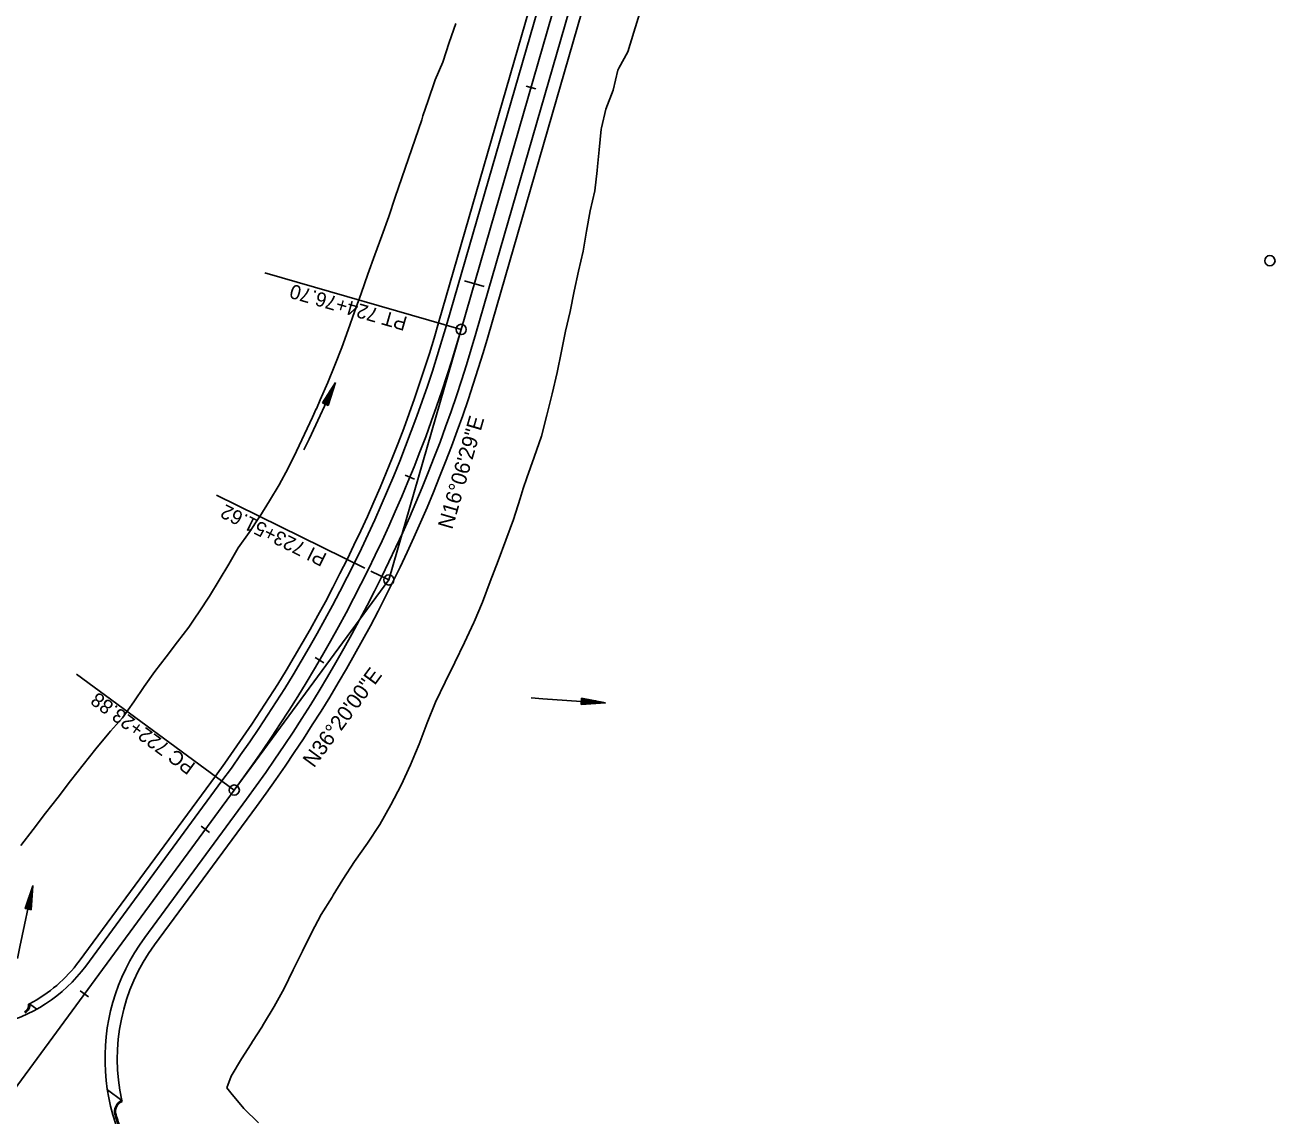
# Model space of a CAD drawing. Extents: x 1300404 to 1323571, y 234004 to 252077.
# Drawn here: x 1311254 to 1311867, y 240523 to 241056 of the extents above; entities that cross this region are included whole.
import ezdxf

# ---------------------------------------------------------------- set-up
doc = ezdxf.new("R2010")
doc.units = 0
for name, color, linetype in [('R_Const Limits', 7, 'Continuous'), ('R_Curb', 7, 'Continuous'), ('R_Flow Arrows', 7, 'Continuous'), ('R_Horz Alg Annot', 7, 'Continuous'), ('R_Horz Alg Annot Leader', 7, 'Continuous'), ('R_Horz Alg Major Ticks', 7, 'Continuous'), ('R_Horz Alg Minor Ticks', 7, 'Continuous'), ('R_Horz Alg Tangents', 7, 'Continuous'), ('R_Horz Alg Tangents Text', 7, 'Continuous'), ('R_Lane Edge', 7, 'Continuous'), ('R_Proposed', 7, 'Continuous'), ('R_Shoulder', 7, 'Continuous')]:
    doc.layers.add(name, color=color, linetype=linetype)

msp = doc.modelspace()

# ---------------------------------------------------------------- linework, layer by layer
at = {"layer": 'R_Const Limits'}
for points in [[(1311555.44, 241062.48), (1311552.59, 241052.89), (1311549.67, 241043.33), (1311545.17, 241035.34), (1311544.69, 241034.36), (1311542.46, 241024.6), (1311538.76, 241015.26), (1311536.65, 241006.06), (1311536.59, 241005.47), (1311535.54, 240995.37), (1311534.82, 240987.2), (1311534.65, 240985.22), (1311533.46, 240975.15), (1311531.22, 240965.39), (1311529.45, 240955.49), (1311527.66, 240945.6), (1311525.48, 240935.82), (1311523.25, 240926.06), (1311521.35, 240916.2), (1311519.03, 240906.46), (1311517.1, 240896.61), (1311515, 240886.31), (1311512.61, 240875.83), (1311510.02, 240865.39), (1311507.27, 240854.99), (1311503.78, 240844.83), (1311500.22, 240834.68), (1311498.32, 240829.38), (1311498.32, 240829.38), (1311496.87, 240824.45), (1311493.62, 240814.17), (1311489.82, 240804.08), (1311486.09, 240793.95), (1311482.24, 240783.86), (1311478.43, 240773.73), (1311474.33, 240764.06), (1311474.19, 240763.78), (1311469.62, 240753.98), (1311464.94, 240744.22), (1311460.1, 240734.54), (1311455.46, 240724.73), (1311451.41, 240714.56), (1311447.49, 240704.25), (1311445.71, 240700.01), (1311445.7, 240700.01), (1311443.18, 240694.12), (1311438.54, 240684.15), (1311433.48, 240674.4), (1311428.12, 240664.82), (1311422.11, 240655.66), (1311415.82, 240646.7), (1311409.97, 240637.86), (1311405.38, 240630.29), (1311404.76, 240629.28), (1311399.38, 240620.82), (1311394.77, 240611.8), (1311390.23, 240602.72), (1311385.79, 240593.58), (1311381.29, 240584.48), (1311376.36, 240575.69), (1311371.2, 240567.07), (1311370.33, 240565.6), (1311365.88, 240558.57), (1311365.17, 240557.39), (1311360.46, 240550.14), (1311355.33, 240541.5), (1311353.2, 240535.86)], [(1311252.34, 240654.48), (1311258.42, 240662.43), (1311264.52, 240670.35), (1311270.65, 240678.26), (1311276.74, 240686.19), (1311282.96, 240694.03), (1311289.17, 240701.88), (1311295.49, 240709.64), (1311296.22, 240710.58), (1311302.18, 240717.14), (1311307.63, 240724.85), (1311312.72, 240732.38), (1311318.04, 240739.75), (1311323.55, 240747), (1311329.13, 240754.24), (1311334.56, 240761.58), (1311337.63, 240765.92), (1311337.63, 240765.93), (1311339.76, 240769.09), (1311344.79, 240776.72), (1311349.57, 240784.5), (1311354.22, 240792.37), (1311358.78, 240800.3), (1311364.13, 240807.82), (1311369.23, 240815.52), (1311369.37, 240815.75), (1311374.13, 240823.35), (1311378.85, 240831.29), (1311383.24, 240839.41), (1311387.29, 240847.7), (1311391.33, 240856), (1311395.23, 240864.38), (1311397.07, 240868.37), (1311397.08, 240868.38), (1311399.03, 240872.81), (1311402.68, 240881.31), (1311406.21, 240889.87), (1311409.51, 240898.52), (1311412.73, 240907.22), (1311415.81, 240915.96), (1311419.03, 240924.93), (1311422.31, 240934.39), (1311425.65, 240943.83), (1311429.1, 240953.25), (1311432.51, 240962.67), (1311435.75, 240972.14), (1311438.99, 240981.62), (1311442.24, 240991.09), (1311445.44, 241000.57), (1311448.67, 241010.05), (1311449.29, 241011.9), (1311451.85, 241019.54), (1311455.03, 241029.03), (1311455.21, 241029.58), (1311458.96, 241038.3), (1311462.11, 241047.8), (1311465.46, 241057.24)], [(1311353.2, 240535.86), (1311355.14, 240533.39), (1311361.62, 240525.75), (1311368.7, 240518.68)]]:
    msp.add_lwpolyline(points, dxfattribs=at)
at = {"layer": 'R_Curb'}
for centre, radius, start, end in [((1311252.75, 240576.22), 3.5, 294.48881, 9.25521), ((1311252.75, 240576.22), 4, 294.48881, 11.59092), ((1311304.27, 240524.22), 6, 113.98173, 196.20549), ((1311304.27, 240524.22), 5.5, 115.0194, 196.20549), ((1311393.58, 240550.17), 99, 196.20549, 199.75076), ((1311393.58, 240550.17), 98.5, 196.20549, 200.41529)]:
    msp.add_arc(centre, radius, start, end, dxfattribs=at)
at = {"layer": 'R_Flow Arrows'}
for p, q in [((1311400.13, 240871.35), (1311406.39, 240881.42)), ((1311402.9, 240870.09), (1311406.39, 240881.42)), ((1311402.9, 240870.09), (1311400.13, 240871.35)), ((1311526.79, 240723.64), (1311526.97, 240726.67)), ((1311526.79, 240723.64), (1311538.61, 240724.45)), ((1311526.97, 240726.67), (1311538.61, 240724.45)), ((1311254.41, 240623.66), (1311258.21, 240634.88)), ((1311257.39, 240623.06), (1311258.21, 240634.88)), ((1311254.41, 240623.66), (1311257.39, 240623.06))]:
    msp.add_line(p, q, dxfattribs=at)
for points in [[(1311391.03, 240848.31), (1311393.49, 240853.53), (1311406.52, 240881.35)], [(1311400.96, 240870.98), (1311403.54, 240876.63), (1311403.88, 240877.39)], [(1311401.24, 240870.85), (1311403.81, 240876.51), (1311405.13, 240879.41)], [(1311401.79, 240870.6), (1311404.37, 240876.26), (1311405.68, 240879.16)], [(1311400.41, 240871.23), (1311401.38, 240873.37)], [(1311400.68, 240871.1), (1311402.63, 240875.38)], [(1311402.07, 240870.47), (1311404.65, 240876.13), (1311404.99, 240876.89)], [(1311402.34, 240870.35), (1311404.29, 240874.62)], [(1311402.62, 240870.22), (1311403.6, 240872.36)], [(1311502.2, 240726.87), (1311507.94, 240726.45), (1311538.59, 240724.3)], [(1311526.84, 240724.55), (1311533.05, 240724.18), (1311533.88, 240724.13)], [(1311526.86, 240724.85), (1311533.07, 240724.48), (1311536.24, 240724.3)], [(1311526.9, 240725.46), (1311533.1, 240725.09), (1311536.28, 240724.91)], [(1311526.91, 240725.76), (1311533.12, 240725.39), (1311533.95, 240725.34)], [(1311526.93, 240726.06), (1311531.62, 240725.78)], [(1311526.95, 240726.37), (1311529.3, 240726.23)], [(1311526.8, 240723.94), (1311529.15, 240723.8)], [(1311526.82, 240724.24), (1311531.51, 240723.96)], [(1311250.72, 240599.22), (1311251.9, 240604.86), (1311258.26, 240634.92)], [(1311255.6, 240623.42), (1311256.83, 240629.52), (1311257.46, 240632.63)], [(1311255.01, 240623.54), (1311255.93, 240628.15)], [(1311255.31, 240623.48), (1311256.53, 240629.58), (1311256.7, 240630.39)], [(1311256.2, 240623.3), (1311257.42, 240629.39), (1311258.06, 240632.51)], [(1311256.5, 240623.24), (1311257.72, 240629.33), (1311257.89, 240630.15)], [(1311256.8, 240623.18), (1311257.72, 240627.79)], [(1311254.71, 240623.6), (1311255.17, 240625.9)], [(1311257.1, 240623.12), (1311257.56, 240625.42)]]:
    msp.add_lwpolyline(points, dxfattribs=at)
at = {"layer": 'R_Horz Alg Annot Leader'}
for points in [[(1311468.01, 240907.35), (1311371.93, 240935.09)], [(1311468.01, 240907.35), (1311371.93, 240935.09)], [(1311420.75, 240790.45), (1311348.2, 240826.18)], [(1311420.75, 240790.45), (1311348.2, 240826.18)], [(1311432.57, 240784.63), (1311423.68, 240789.01)], [(1311432.57, 240784.63), (1311423.68, 240789.01)], [(1311356.89, 240681.72), (1311279.62, 240738.55)], [(1311356.89, 240681.72), (1311279.62, 240738.55)]]:
    msp.add_lwpolyline(points, dxfattribs=at)
at = {"layer": 'R_Horz Alg Major Ticks'}
msp.add_lwpolyline([(1311469.67, 240931.12), (1311479.28, 240928.35)], dxfattribs=at)
msp.add_lwpolyline([(1311469.67, 240931.12), (1311479.28, 240928.35)], dxfattribs=at)
at = {"layer": 'R_Horz Alg Minor Ticks'}
for points in [[(1311499.82, 241026.5), (1311504.62, 241025.11)], [(1311499.82, 241026.5), (1311504.62, 241025.11)], [(1311440.51, 240835.89), (1311445.14, 240833.99)], [(1311440.51, 240835.89), (1311445.14, 240833.99)], [(1311396.48, 240746.58), (1311400.8, 240744.06)], [(1311396.48, 240746.58), (1311400.8, 240744.06)], [(1311340.72, 240663.96), (1311344.75, 240661)], [(1311340.72, 240663.96), (1311344.75, 240661)], [(1311281.47, 240583.41), (1311285.5, 240580.44)], [(1311281.47, 240583.41), (1311285.5, 240580.44)]]:
    msp.add_lwpolyline(points, dxfattribs=at)
at = {"layer": 'R_Horz Alg Tangents'}
for p, q in [((1311432.57, 240784.63), (1311468.01, 240907.35)), ((1311432.57, 240784.63), (1311468.01, 240907.35)), ((1311356.89, 240681.72), (1311432.57, 240784.63)), ((1311356.89, 240681.72), (1311432.57, 240784.63))]:
    msp.add_line(p, q, dxfattribs=at)
at = {"layer": 'R_Lane Edge'}
for p, q in [((1311460.8, 240909.43), (1311563.29, 241264.31)), ((1311475.21, 240905.27), (1311577.7, 241260.15)), ((1311284.15, 240595.49), (1311350.84, 240686.17)), ((1311313.02, 240609.42), (1311362.93, 240677.28)), ((1311256.67, 240577.02), (1311256.2, 240576.78)), ((1311256.67, 240577.02), (1311260.23, 240574.4)), ((1311301.83, 240529.7), (1311294.75, 240534.91)), ((1311301.95, 240529.2), (1311301.83, 240529.7))]:
    msp.add_line(p, q, dxfattribs=at)
for centre, radius, start, end in [((1310779.93, 241106.06), 708.7, 323.66667, 343.89183), ((1310779.93, 241106.06), 723.7, 323.66667, 343.89183), ((1311393.58, 240550.17), 100, 143.66667, 223.66667), ((1311223.73, 240639.92), 75, 282.23981, 323.66667)]:
    msp.add_arc(centre, radius, start, end, dxfattribs=at)
at = {"layer": 'R_Proposed'}
for p, q in [((1311468.01, 240907.35), (1311570.49, 241262.23)), ((1311468.01, 240907.35), (1311570.49, 241262.23)), ((1311241.2, 240524.43), (1311356.89, 240681.72)), ((1311241.2, 240524.43), (1311356.89, 240681.72))]:
    msp.add_line(p, q, dxfattribs=at)
for centre in [(1311864.02, 240941.01), (1311468.01, 240907.35), (1311468.01, 240907.35), (1311432.57, 240784.63), (1311432.57, 240784.63), (1311356.89, 240681.72), (1311356.89, 240681.72)]:
    msp.add_circle(centre, 2.5, dxfattribs=at)
msp.add_arc((1310779.93, 241106.06), 716.2, 323.66667, 343.89183, dxfattribs=at)
msp.add_arc((1310779.93, 241106.06), 716.2, 323.66667, 343.89183, dxfattribs=at)
at = {"layer": 'R_Shoulder'}
for p, q in [((1311456.96, 240910.54), (1311559.45, 241265.42)), ((1311480.98, 240903.6), (1311583.46, 241258.48)), ((1311280.93, 240597.86), (1311347.62, 240688.54)), ((1311317.85, 240605.87), (1311367.76, 240673.73))]:
    msp.add_line(p, q, dxfattribs=at)
for centre, radius, start, end in [((1310779.93, 241106.06), 704.7, 323.66667, 343.89183), ((1310779.93, 241106.06), 729.7, 323.66667, 343.89183), ((1311393.58, 240550.17), 94, 143.66667, 192.57952), ((1311223.73, 240639.92), 71, 297.63688, 323.66667)]:
    msp.add_arc(centre, radius, start, end, dxfattribs=at)

# ---------------------------------------------------------------- texts
at = {"layer": 'R_Horz Alg Annot'}
for s, rotation, p in [('PT 724+76.70', 163.89183, (1311442.1, 240913.27)), ('PT 724+76.70', 163.89183, (1311442.1, 240913.27)), ('PI 723+51.62', 153.77925, (1311402.73, 240797.18)), ('PI 723+51.62', 153.77925, (1311402.73, 240797.18)), ('PC 722+23.88', 143.66667, (1311338.41, 240694.41)), ('PC 722+23.88', 143.66667, (1311338.41, 240694.41))]:
    msp.add_text(s, height=7, rotation=rotation, dxfattribs=at).set_placement(p)
at = {"layer": 'R_Horz Alg Tangents Text'}
for s, rotation, p in [('N16%%d06\'29"E', 73.89183, (1311463.62, 240809.02)), ('N16%%d06\'29"E', 73.89183, (1311463.62, 240809.02)), ('N36%%d20\'00"E', 53.66667, (1311395.89, 240692.25)), ('N36%%d20\'00"E', 53.66667, (1311395.89, 240692.25))]:
    msp.add_text(s, height=7.5, rotation=rotation, dxfattribs=at).set_placement(p)

doc.saveas('drawing.dxf')
